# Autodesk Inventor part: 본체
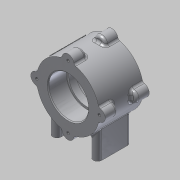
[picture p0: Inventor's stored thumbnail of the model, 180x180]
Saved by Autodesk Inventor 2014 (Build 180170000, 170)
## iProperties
Created: 2015-03
Part Number: 본체
Material: 알루미늄 6061
Document SubType Name: Modeling
Designer: MYHOME
Mass: 450.776 g
Surface Area: 332.745 cm^2
Volume: 166.338 cm^3
Density: 2.71 g/cm^3
Appearance: 알루미늄 - 평지
Author: MYHOME
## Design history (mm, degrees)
sketch "스케치2"
  geometry: C1 r 37 at (0, 56); 1 further point
  constraints: 1 centre point, 1 vertical alignment
  dimensions: "d0" = 74 diameter of C1; "d1" = 56 distance of point (0, 0) C1.centre
extrude "돌출1" new body sketch "스케치2" stored distance "d2" = 52; taper "d3" = 0 deg
sketch "스케치3"
  geometry: L1 (0, 0)-(0, 37); C1 r 7 at (0, 37); 1 further point
  constraints: 2 end point, 1 centre point, 1 coincident, 1 vertical, 1 vertical alignment, 1 other
  dimensions: "d4" = 7 radius of C1
extrude "돌출2" join sketch "스케치3" distance "d5" = 15; taper "d6" = 0 deg
sketch "스케치4"
  geometry: C1 r 23.5 at (0, 56); A1 r 37 centre (0, 56) between (-6.969, 92.338) and (-36.338, 62.969) reference; 1 further point
  constraints: 1 centre point, 1 coincident
  dimensions: "d10" = 47 diameter of C1
extrude "돌출3" cut sketch "스케치4" distance "d11" = 22; taper "d12" = 0 deg
sketch "스케치5"
  geometry: A1 r 7 centre (0, 19) between (-6.969, 19.662) and (6.969, 19.662) reference; A2 r 7 centre (37, 56) between (36.338, 49.031) and (36.338, 62.969) reference; A3 r 7 centre (0, 93) between (6.969, 92.338) and (-6.969, 92.338) reference; A4 r 7 centre (-37, 56) between (-36.338, 62.969) and (-36.338, 49.031) reference; 5 further points
  constraints: 4 coincident
hole "구멍1" sketch "스케치5" at (0, 93), (37, 56), (0, 19), (-37, 56) diameter "d13" = 3.242; stored, may be unused: countersink angle "d17" = 90 deg, drill point angle "d19" = 118 deg; dims "d14" = 8, "d15" = 4, "d16" = 2, "d18" = 11
sketch "스케치6"
  geometry: C1 r 23.5 at (0, 0) reference; C2 r 21 at (0, 0); 1 further point
  constraints: 1 centre point, 1 coincident
  dimensions: "d20" = 42 diameter of C2
extrude "돌출4" cut sketch "스케치6" distance "d21" = 10; taper "d22" = 0 deg
sketch "스케치7"
  geometry: L1 (-24, 15)-(-24, -15); L2 (-29, 15)-(-29, -15); L3 (-19, -15)-(-19, 15); L4 (24, 15)-(24, -15); L5 (19, 15)-(19, -15); L6 (29, -15)-(29, 15); A1 r 5 centre (-24, 15) between (-19, 15) and (-29, 15); A2 r 5 centre (-24, -15) between (-29, -15) and (-19, -15); A3 r 5 centre (24, 15) between (29, 15) and (19, 15); A4 r 5 centre (24, -15) between (19, -15) and (29, -15); 3 further points
  constraints: 16 end point, 8 point on circle, 8 tangent, 4 centre point, 3 parallel, 2 horizontal alignment, 2 midpoint, 1 vertical
  dimensions: "d23" = 48 distance of point (24, 0) point (-24, 0); "d24" = 10 distance between parallel lines of L6 L5; "d25" = 10 distance between parallel lines of L2 L3; "d26" = 40 dimension on A4 A3; "d27" = 40 dimension on A2 A1; "d28" = 24 distance of point (24, 0) point (0, 0)
extrude "돌출5" join sketch "스케치7" stored distance "d29" = 10; taper "d30" = 0 deg
sketch "스케치8"
  geometry: A1 r 5 centre (-24, 15) between (-19, 15) and (-29, 15) reference; A2 r 5 centre (-24, -15) between (-29, -15) and (-19, -15) reference; A3 r 5 centre (24, 15) between (29, 15) and (19, 15) reference; A4 r 5 centre (24, -15) between (19, -15) and (29, -15) reference; 5 further points
  constraints: 4 coincident
hole "구멍2" sketch "스케치8" at (-24, 15), (-24, -15), (24, 15), (24, -15) diameter "d31" = 4.134; stored, may be unused: countersink angle "d35" = 90 deg, drill point angle "d37" = 118 deg; dims "d32" = 6, "d33" = 4, "d34" = 2, "d36" = 8
sketch "스케치9"
  geometry: L1 (0, 56)-(0, 93); L2 (0, 56)-(26.163, 82.163); A1 r 37 centre (0, 56) between (36.338, 62.969) and (6.969, 92.338) reference; A2 r 37 centre (0, 56) between (6.969, 92.338) and (-6.969, 92.338) reference; 2 further points
  constraints: 4 end point, 2 point on circle, 1 coincident
  dimensions: "d38" = 45 deg angle of L1 L2
node "작업 평면1"
sketch "스케치10"
  geometry: L1 (-15, -36.754)-(15, -36.754) reference; L2 (15, -35.885)-(-15, -35.885) reference; L3 (-15, -9.015)-(15, -9.015) reference; L4 (15, 4.258)-(-15, 4.258) reference; L5 (26, -30.622)-(11, -30.622) reference; L6 (11, -30.622)-(11, -20.767) reference; L7 (11, -20.767)-(26, -20.767) reference; L8 (26, 20.767)-(26, -20.767) reference; L9 (26, 20.767)-(11, 20.767) reference; L10 (11, 20.767)-(11, 30.622) reference; L11 (11, 30.622)-(26, 30.622) reference; L12 (26, 30.622)-(26, 30.622) reference; L13 (26, 30.622)-(11, 30.622) reference; L14 (11, 30.622)-(11, 20.767) reference; L15 (11, 20.767)-(26, 20.767) reference; L16 (26, -20.767)-(26, 20.767) reference; L17 (26, -20.767)-(11, -20.767) reference; L18 (11, -20.767)-(11, -30.622) reference; L19 (11, -30.622)-(26, -30.622) reference; L20 (26, -30.622)-(26, -30.622) reference; L21 (-26, -20.767)-(-11, -20.767) reference; L22 (-11, -20.767)-(-11, -30.622) reference; L23 (-11, -30.622)-(-26, -30.622) reference; L24 (-26, -30.622)-(-26, -30.622) reference; L25 (-26, -30.622)-(-11, -30.622) reference; L26 (-11, -30.622)-(-11, -20.767) reference; L27 (-11, -20.767)-(-26, -20.767) reference; L28 (-26, 20.767)-(-26, -20.767) reference; L29 (-26, 20.767)-(-11, 20.767) reference; L30 (-11, 20.767)-(-11, 30.622) reference; L31 (-11, 30.622)-(-26, 30.622) reference; L32 (-26, 30.622)-(-26, 30.622) reference; L33 (-26, 30.622)-(-11, 30.622) reference; L34 (-11, 30.622)-(-11, 20.767) reference; L35 (-11, 20.767)-(-26, 20.767) reference; L36 (-26, -20.767)-(-26, 20.767) reference; 3 further points
  constraints: 4 vertical alignment, 1 coincident, 1 other
feature "엠보싱1" sketch "스케치10" dims "d39" = 0.5, "d40" = 0
fillet "모깎기1" dims "d41" = 3
fillet "모깎기2" dims "d42" = 3
fillet "모깎기3" dims "d43" = 3
fillet "모깎기4" dims "d44" = 3
fillet "모깎기5" dims "d45" = 3
fillet "모깎기6" dims "d46" = 3
chamfer "모따기1" distance "d47" = 1; stored, may be unused: second distance "d48" = 2, angle "d49" = 45 deg
fillet "모깎기7" dims "d50" = 0.3
node "솔리드1"
pattern_circular "원형 패턴1" dims angle "d8" = 360 deg
mirror "대칭1"
node "투영된 루프1"
